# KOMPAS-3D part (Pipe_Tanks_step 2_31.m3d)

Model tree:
1. X Axis
2. Y Axis
3. Z Axis  (labels: Pipe Dn 50)
     Òîëùèíà ñòåíêè 1 = 1

Referenced files in C:\Documents and Settings\kashirsky\Мои документы\Camtasia Studio\Pipelines3D\Tanks\: Tanks_step 2.a3d
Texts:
  Pipe Dn 50
  Steel ASTM A295
  Three Point Plane
  Plane at Angle
  Line and Point Plane
  Axis through Two Vertices
  Axis of Feature
  Axis of Conical Surface
  Axis through Edge
  Trim by Surface
  Trim by Sketch
  Feature with No History
  Intersection Axis of Two Planes
  Two Line Plane
  Line and Face Plane
  Bend by line
  Hole in sheet body
  Cut in sheet body
  Point in CM
  Linear Dimension from Line to Point
  Surface Finish Symbol
  Geometric Tolerance Symbol
  Leader #1
  Leader #2
  Leader #3
  Shape Deviations and Datum
  Node point number
  Mark of coordination axis
  Node point designation
  Mark/Reference designation with leader
  Mark/reference designation on line
  Mark/Reference designation without leader
  Plane of section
